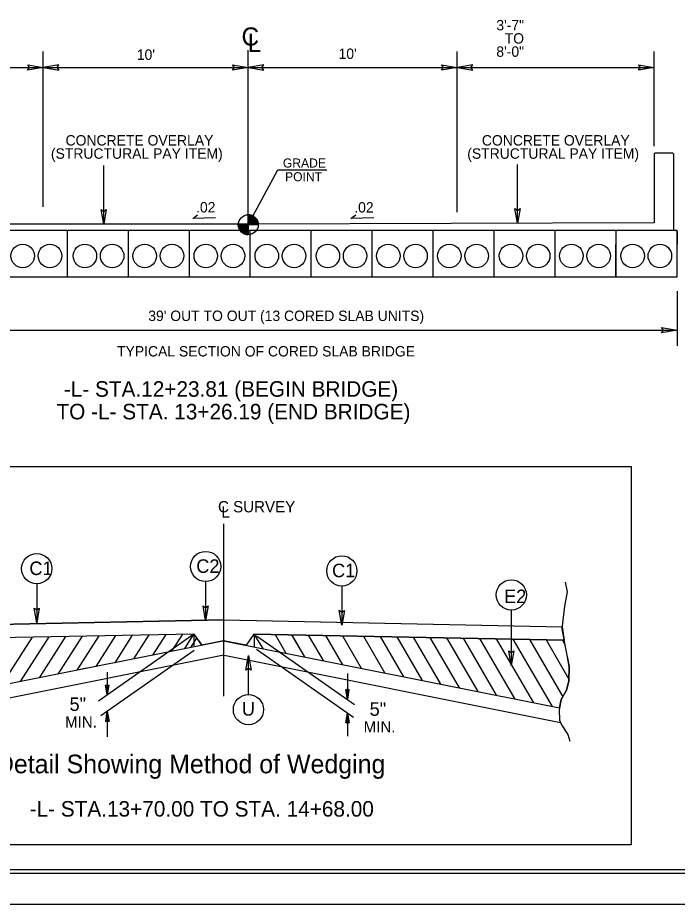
# Model space of a CAD drawing. Extents: x 1818040 to 1825768, y 638918 to 648046.
# Drawn here: x 1820696 to 1821171, y 645383 to 646022 of the extents above; entities that cross this region are included whole.
import ezdxf

# ---------------------------------------------------------------- set-up
doc = ezdxf.new("R2010")
doc.units = 0
for name, color, linetype in [('Default', 7, 'Continuous'), ('Old_Level_1', 7, 'Continuous'), ('Sheet Data Field CELL', 7, 'Continuous'), ('Sheet Plot Border Inside CELL', 7, 'Continuous'), ('Sheet Plot Border Outside CELL', 7, 'Continuous'), ('Sheet Typical CELL', 7, 'Continuous'), ('Typical Bridge Rail CELL', 7, 'Continuous'), ('Typical Detail Wedge2 CELL', 7, 'Continuous'), ('Typical Grade Point Symbol CELL', 7, 'Continuous'), ('Typical ID Circle CELL', 7, 'Continuous'), ('Typical Terminator CELL', 7, 'Continuous'), ('Typical Text Centerline CELL', 7, 'Continuous'), ('Typical Text General CELL', 7, 'Continuous'), ('Typical Text Grade Point CELL', 7, 'Continuous'), ('Typical Text ID Circle CELL', 7, 'Continuous')]:
    doc.layers.add(name, color=color, linetype=linetype)

msp = doc.modelspace()

# ---------------------------------------------------------------- linework, layer by layer
at = {"layer": 'Default'}
for p, q in [((1820714.57, 645885.64), (1820714.57, 645997.66)), ((1820862.17, 645872.84), (1820862.17, 645998.53)), ((1821012.56, 645881.99), (1821012.56, 645997.66)), ((1821154.38, 645929.41), (1821154.38, 645997.66)), ((1820619.19, 645986.11), (1820714.57, 645986.11)), ((1820714.57, 645986.11), (1820772.68, 645986.11)), ((1820772.68, 645986.11), (1820862.17, 645986.11)), ((1820862.17, 645986.11), (1820905.72, 645986.11)), ((1820905.72, 645986.11), (1821012.56, 645986.11)), ((1821012.56, 645986.11), (1821037.24, 645986.11)), ((1821037.24, 645986.11), (1821154.38, 645986.11)), ((1820758.09, 645873.14), (1820758.09, 645915.5)), ((1821056.03, 645873.89), (1821056.03, 645916.25)), ((1820862.17, 645872.84), (1820883.43, 645912.45)), ((1820822.22, 645877.37), (1820825.64, 645879.93)), ((1820838.66, 645877.75), (1820822.22, 645877.37)), ((1820936.12, 645877.3), (1820939.53, 645879.87)), ((1820952.56, 645877.69), (1820936.12, 645877.3)), ((1820602.6, 645869), (1821170.98, 645869)), ((1820862.17, 645873.14), (1820619.19, 645873.14)), ((1820731.69, 645869), (1820731.69, 645835.41)), ((1820775.59, 645869), (1820775.59, 645835.41)), ((1820819.49, 645869), (1820819.49, 645835.41)), ((1821154.38, 645874.27), (1820862.17, 645873.14)), ((1820863.39, 645869), (1820863.39, 645835.41)), ((1820907.29, 645869), (1820907.29, 645835.41)), ((1820951.19, 645869), (1820951.19, 645835.41)), ((1820995.09, 645869), (1820995.09, 645835.41)), ((1821038.99, 645869), (1821038.99, 645835.41)), ((1821082.89, 645869), (1821082.89, 645835.41)), ((1821126.93, 645869), (1821126.93, 645835.41)), ((1821170.98, 645835.41), (1821170.98, 645869)), ((1821126.93, 645835.41), (1821126.93, 645858.57)), ((1820602.6, 645835.41), (1821170.98, 645835.41)), ((1821170.98, 645824.95), (1821170.98, 645785.67)), ((1820602.56, 645796.99), (1821170.98, 645796.99))]:
    msp.add_line(p, q, dxfattribs=at)
for centre in [(1820699.72, 645850.36), (1820719.34, 645850.36), (1820744.52, 645850.36), (1820764.15, 645850.36), (1820787.62, 645850.36), (1820807.25, 645850.36), (1820831.57, 645850.36), (1820851.2, 645850.36), (1820875.52, 645850.36), (1820895.15, 645850.36), (1820919.47, 645850.36), (1820939.1, 645850.36), (1820962.99, 645850.36), (1820982.62, 645850.36), (1821006.94, 645850.36), (1821026.57, 645850.36), (1821051.32, 645850.36), (1821070.95, 645850.36), (1821094.84, 645850.36), (1821114.47, 645850.36), (1821138.89, 645850.36), (1821158.52, 645850.36)]:
    msp.add_circle(centre, 8.47, dxfattribs=at)
at = {"layer": 'Old_Level_1'}
msp.add_lwpolyline([(1820578.56, 645698.83), (1821137.94, 645698.83), (1821137.94, 645426.3), (1820578.56, 645426.3)], close=True, dxfattribs=at)
at = {"layer": 'Sheet Plot Border Inside CELL'}
msp.add_lwpolyline([(1822072.43, 646461.05), (1820405.93, 646461.05), (1820405.93, 645405.95), (1822072.43, 645405.95)], close=True, dxfattribs=at)
at = {"layer": 'Sheet Plot Border Outside CELL'}
msp.add_lwpolyline([(1822076.93, 646483.5), (1820392.93, 646483.5), (1820392.93, 645383.5), (1822076.93, 645383.5)], close=True, dxfattribs=at)
at = {"layer": 'Sheet Typical CELL'}
msp.add_line((1820392.93, 645383.5), (1822076.93, 645383.5), dxfattribs=at)
msp.add_lwpolyline([(1822059.93, 646458.5), (1820559.93, 646458.5), (1820559.93, 645408.5), (1822059.93, 645408.5)], close=True, dxfattribs=at)
at = {"layer": 'Typical Bridge Rail CELL'}
for p, q in [((1821154.38, 645923.89), (1821155.11, 645924.62)), ((1821154.38, 645923.89), (1821154.38, 645874.27)), ((1821155.11, 645924.62), (1821167.71, 645924.62)), ((1821167.71, 645924.62), (1821168.37, 645923.96)), ((1821168.37, 645923.96), (1821168.37, 645869)), ((1821168.37, 645869), (1821169.67, 645869)), ((1821169.67, 645869), (1821170.97, 645867.69)), ((1821170.97, 645867.69), (1821170.97, 645858.57))]:
    msp.add_line(p, q, dxfattribs=at)
at = {"layer": 'Typical Detail Wedge2 CELL'}
for p, q in [((1820844.67, 645533.44), (1820844.67, 645657.51)), ((1820844.67, 645533.44), (1820844.67, 645618.17)), ((1820844.66, 645588.25), (1820601.17, 645583.39)), ((1820601.17, 645583.39), (1820844.66, 645588.25)), ((1820844.66, 645588.25), (1821088.18, 645583.39)), ((1820844.69, 645588.25), (1821088.18, 645583.39)), ((1821088.18, 645583.39), (1821089.57, 645573.6)), ((1820823.31, 645578.07), (1820599.78, 645573.6)), ((1820823.31, 645578.07), (1820599.78, 645573.6)), ((1820706.45, 645575.74), (1820684.28, 645541.12)), ((1820718.48, 645575.98), (1820697.9, 645543.85)), ((1820730.51, 645576.22), (1820711.52, 645546.57)), ((1820742.54, 645576.46), (1820725.14, 645549.3)), ((1820754.57, 645576.7), (1820738.76, 645552.02)), ((1820766.59, 645576.94), (1820752.38, 645554.75)), ((1820823.03, 645577.89), (1820754.42, 645529.84)), ((1820778.62, 645577.18), (1820766, 645557.47)), ((1820790.65, 645577.42), (1820779.62, 645560.2)), ((1820802.68, 645577.66), (1820793.24, 645562.92)), ((1820814.71, 645577.9), (1820806.86, 645565.65)), ((1820816.39, 645567.66), (1820822.99, 645577.98)), ((1820825.05, 645575.51), (1820820.48, 645568.37)), ((1820822.99, 645577.98), (1820822.99, 645569.49)), ((1820828.78, 645570.05), (1820823.31, 645578.07)), ((1820823.31, 645577.81), (1820828.78, 645570.05)), ((1820866.21, 645578.07), (1820860.56, 645570.05)), ((1820866.21, 645578.07), (1820860.56, 645570.05)), ((1820865.85, 645577.89), (1820866.2, 645577.87)), ((1820866.21, 645578.07), (1821089.57, 645573.6)), ((1821089.57, 645573.6), (1820866.21, 645578.07)), ((1820872.96, 645567.66), (1820866.35, 645577.98)), ((1820866.35, 645577.98), (1820866.35, 645568.64)), ((1820868.07, 645576.77), (1820938.76, 645527.27)), ((1820881.44, 645577.77), (1820889.31, 645564.28)), ((1820893.39, 645577.53), (1820902.69, 645561.6)), ((1820893.59, 645577.25), (1820902.71, 645561.64)), ((1820905.34, 645577.29), (1820916.06, 645558.93)), ((1820917.75, 645577.04), (1820930, 645556.01)), ((1820929.91, 645576.8), (1820943.53, 645553.43)), ((1820945.13, 645576.49), (1820960.57, 645550.02)), ((1820957.08, 645576.25), (1820973.94, 645547.34)), ((1820969.03, 645576.01), (1820987.31, 645544.67)), ((1820980.98, 645575.78), (1821000.67, 645542)), ((1820992.92, 645575.54), (1821014.04, 645539.32)), ((1821004.87, 645575.3), (1821027.41, 645536.65)), ((1821016.82, 645575.06), (1821040.77, 645533.98)), ((1821028.76, 645574.82), (1821054.14, 645531.3)), ((1821040.71, 645574.58), (1821067.5, 645528.63)), ((1821052.66, 645574.34), (1821080.87, 645525.96)), ((1820845.03, 645573.28), (1820603, 645524.86)), ((1820844.31, 645573.28), (1820828.78, 645570.05)), ((1820844.31, 645573.28), (1821086.35, 645524.86)), ((1820860.56, 645570.05), (1820844.31, 645573.28)), ((1821064.6, 645574.1), (1821088.61, 645532.93)), ((1821076.55, 645573.86), (1821093.06, 645545.56)), ((1821088.5, 645573.63), (1821089.98, 645571.08)), ((1820844.58, 645562.86), (1820602.92, 645514.52)), ((1820823.19, 645566.15), (1820756.05, 645519.14)), ((1820844.76, 645562.86), (1821086.99, 645514.41)), ((1820867.97, 645567.15), (1820937.97, 645518.15)), ((1820745.78, 645553.43), (1820738.15, 645551.9)), ((1820760.67, 645550.54), (1820760.67, 645534.23)), ((1820933.59, 645549.6), (1820933.59, 645530.9)), ((1820760.67, 645534.23), (1820759.41, 645541.38)), ((1820760.67, 645540.45), (1820759.41, 645541.38)), ((1820760.67, 645534.23), (1820759.59, 645541.24)), ((1820759.77, 645541.11), (1820760.67, 645534.23)), ((1820760.67, 645534.23), (1820759.95, 645540.98)), ((1820760.13, 645540.85), (1820760.67, 645534.23)), ((1820760.67, 645534.23), (1820760.31, 645540.72)), ((1820760.49, 645540.58), (1820760.67, 645534.23)), ((1820760.67, 645534.23), (1820761.94, 645541.38)), ((1820761.94, 645541.38), (1820760.67, 645540.45)), ((1820761.76, 645541.24), (1820760.67, 645534.23)), ((1820760.67, 645534.23), (1820761.57, 645541.11)), ((1820761.39, 645540.98), (1820760.67, 645534.23)), ((1820760.67, 645534.23), (1820761.21, 645540.85)), ((1820761.03, 645540.72), (1820760.67, 645534.23)), ((1820760.67, 645534.23), (1820760.85, 645540.58)), ((1820760.67, 645540.45), (1820760.67, 645534.23)), ((1820933.59, 645530.9), (1820932.33, 645538.06)), ((1820933.59, 645537.13), (1820932.33, 645538.06)), ((1820933.59, 645530.9), (1820932.51, 645537.92)), ((1820932.69, 645537.79), (1820933.59, 645530.9)), ((1820933.59, 645530.9), (1820932.87, 645537.65)), ((1820933.04, 645537.52), (1820933.59, 645530.9)), ((1820933.59, 645530.9), (1820933.22, 645537.39)), ((1820933.4, 645537.26), (1820933.59, 645530.9)), ((1820933.59, 645530.9), (1820934.85, 645538.06)), ((1820934.85, 645538.06), (1820933.59, 645537.13)), ((1820934.66, 645537.92), (1820933.59, 645530.9)), ((1820933.59, 645530.9), (1820934.49, 645537.79)), ((1820934.31, 645537.65), (1820933.59, 645530.9)), ((1820933.59, 645530.9), (1820934.13, 645537.52)), ((1820933.95, 645537.39), (1820933.59, 645530.9)), ((1820933.59, 645530.9), (1820933.77, 645537.26)), ((1820933.59, 645537.13), (1820933.59, 645530.9)), ((1820760.67, 645522.37), (1820759.41, 645515.21)), ((1820759.59, 645515.35), (1820760.67, 645522.37)), ((1820760.67, 645522.37), (1820759.77, 645515.48)), ((1820759.95, 645515.62), (1820760.67, 645522.37)), ((1820760.67, 645522.37), (1820760.13, 645515.75)), ((1820760.31, 645515.87), (1820760.67, 645522.37)), ((1820760.67, 645522.37), (1820760.49, 645516.01)), ((1820760.67, 645522.37), (1820760.67, 645504)), ((1820760.67, 645522.37), (1820761.94, 645515.21)), ((1820760.67, 645516.14), (1820760.67, 645522.37)), ((1820760.85, 645516.01), (1820760.67, 645522.37)), ((1820760.67, 645522.37), (1820761.03, 645515.87)), ((1820761.21, 645515.75), (1820760.67, 645522.37)), ((1820760.67, 645522.37), (1820761.39, 645515.62)), ((1820761.57, 645515.48), (1820760.67, 645522.37)), ((1820760.67, 645522.37), (1820761.76, 645515.35)), ((1820933.59, 645521.21), (1820932.33, 645514.05)), ((1820932.51, 645514.19), (1820933.59, 645521.21)), ((1820933.59, 645521.21), (1820932.69, 645514.32)), ((1820932.87, 645514.46), (1820933.59, 645521.21)), ((1820933.59, 645521.21), (1820933.04, 645514.59)), ((1820933.22, 645514.71), (1820933.59, 645521.21)), ((1820933.59, 645521.21), (1820933.4, 645514.85)), ((1820933.59, 645521.21), (1820933.59, 645504.47)), ((1820933.59, 645521.21), (1820934.85, 645514.05)), ((1820933.59, 645514.98), (1820933.59, 645521.21)), ((1820933.77, 645514.85), (1820933.59, 645521.21)), ((1820933.59, 645521.21), (1820933.95, 645514.71)), ((1820934.13, 645514.59), (1820933.59, 645521.21)), ((1820933.59, 645521.21), (1820934.31, 645514.46)), ((1820934.49, 645514.32), (1820933.59, 645521.21)), ((1820933.59, 645521.21), (1820934.66, 645514.19)), ((1820759.41, 645515.21), (1820760.67, 645516.14)), ((1820760.67, 645516.14), (1820761.94, 645515.21)), ((1820932.33, 645514.05), (1820933.59, 645514.98)), ((1820933.59, 645514.98), (1820934.85, 645514.05))]:
    msp.add_line(p, q, dxfattribs=at)
for points in [[(1821090.43, 645615.52), (1821091.73, 645608.39), (1821089.79, 645598.25), (1821088.06, 645581.83), (1821090.43, 645568.87), (1821093.24, 645554.83), (1821093.03, 645544.24), (1821091.29, 645537.56), (1821087.41, 645530.85), (1821086.12, 645523.51), (1821086.32, 645516.17), (1821087.62, 645512.71), (1821092.15, 645505.79), (1821093.66, 645501.04)], [(1821086.35, 645524.86), (1821087.41, 645530.85), (1821091.29, 645537.56), (1821093.03, 645544.24), (1821093.24, 645554.83), (1821091.94, 645561.34)]]:
    msp.add_lwpolyline(points, dxfattribs=at)
at = {"layer": 'Typical Grade Point Symbol CELL'}
for p, q in [((1820862.17, 645872.84), (1820862.17, 645880)), ((1820855.01, 645872.84), (1820862.17, 645872.84)), ((1820862.15, 645865.68), (1820862.17, 645872.84)), ((1820862.17, 645872.84), (1820862.15, 645865.68)), ((1820869.33, 645872.84), (1820862.17, 645872.84))]:
    msp.add_line(p, q, dxfattribs=at)
for points in [[(1820862.23, 645880), (1820862.23, 645880), (1820862.23, 645872.84)], [(1820862.37, 645880), (1820862.37, 645872.84)], [(1820862.52, 645879.98), (1820862.52, 645872.84)], [(1820862.66, 645879.98), (1820862.66, 645872.84)], [(1820862.8, 645879.97), (1820862.8, 645872.84)], [(1820862.95, 645879.95), (1820862.95, 645872.84)], [(1820863.09, 645879.93), (1820863.09, 645872.84)], [(1820863.23, 645879.92), (1820863.23, 645872.84)], [(1820863.38, 645879.9), (1820863.38, 645872.84)], [(1820863.52, 645879.87), (1820863.52, 645872.84)], [(1820863.66, 645879.84), (1820863.66, 645872.84)], [(1820863.81, 645879.81), (1820863.81, 645872.84)], [(1820863.95, 645879.78), (1820863.95, 645872.84)], [(1820864.09, 645879.73), (1820864.09, 645872.84)], [(1820864.24, 645879.7), (1820864.24, 645872.84)], [(1820864.38, 645879.65), (1820864.38, 645872.84)], [(1820864.52, 645879.6), (1820864.52, 645872.84)], [(1820864.67, 645879.55), (1820864.67, 645872.84)], [(1820864.81, 645879.49), (1820864.81, 645872.84)], [(1820864.95, 645879.43), (1820864.95, 645872.84)], [(1820865.1, 645879.36), (1820865.1, 645872.84)], [(1820865.24, 645879.3), (1820865.24, 645872.84)], [(1820865.38, 645879.23), (1820865.38, 645872.84)], [(1820865.52, 645879.15), (1820865.52, 645872.84)], [(1820865.67, 645879.08), (1820865.67, 645872.84)], [(1820865.81, 645879), (1820865.81, 645872.84)], [(1820865.95, 645878.92), (1820865.95, 645872.84)], [(1820866.1, 645878.82), (1820866.1, 645872.84)], [(1820866.24, 645878.72), (1820866.24, 645872.84)], [(1820866.38, 645878.61), (1820866.38, 645872.84)], [(1820866.53, 645878.52), (1820866.53, 645872.84)], [(1820866.67, 645878.41), (1820866.67, 645872.84)], [(1820866.81, 645878.28), (1820866.81, 645872.84)], [(1820866.96, 645878.15), (1820866.96, 645872.84)], [(1820867.1, 645878.02), (1820867.1, 645872.84)], [(1820867.24, 645877.88), (1820867.24, 645872.84)], [(1820867.39, 645877.74), (1820867.39, 645872.84)], [(1820867.53, 645877.58), (1820867.53, 645872.84)], [(1820867.67, 645877.4), (1820867.67, 645872.84)], [(1820867.82, 645877.23), (1820867.82, 645872.84)], [(1820867.96, 645877.04), (1820867.96, 645872.84)], [(1820868.1, 645876.83), (1820868.1, 645872.84)], [(1820868.25, 645876.61), (1820868.25, 645872.84)], [(1820868.39, 645876.37), (1820868.39, 645872.84)], [(1820868.53, 645876.12), (1820868.53, 645872.84)], [(1820868.68, 645875.81), (1820868.68, 645872.84)], [(1820868.82, 645875.48), (1820868.82, 645872.84)], [(1820868.96, 645875.08), (1820868.96, 645872.84)], [(1820869.11, 645874.59), (1820869.11, 645872.84)], [(1820855.04, 645872.84), (1820855.04, 645872.06)], [(1820855.18, 645872.84), (1820855.18, 645871.21)], [(1820855.32, 645872.84), (1820855.32, 645870.7)], [(1820855.47, 645872.84), (1820855.47, 645870.27)], [(1820855.61, 645872.84), (1820855.61, 645869.94)], [(1820855.75, 645872.84), (1820855.75, 645869.64)], [(1820855.9, 645872.84), (1820855.9, 645869.37)], [(1820856.04, 645872.84), (1820856.04, 645869.11)], [(1820856.18, 645872.84), (1820856.18, 645868.89)], [(1820856.33, 645872.84), (1820856.33, 645868.68)], [(1820856.47, 645872.84), (1820856.47, 645868.49)], [(1820856.61, 645872.84), (1820856.61, 645868.32)], [(1820856.76, 645872.84), (1820856.76, 645868.14)], [(1820856.9, 645872.84), (1820856.9, 645867.98)], [(1820857.04, 645872.84), (1820857.04, 645867.82)], [(1820857.19, 645872.84), (1820857.19, 645867.68)], [(1820857.33, 645872.84), (1820857.33, 645867.55)], [(1820857.47, 645872.84), (1820857.47, 645867.43)], [(1820857.62, 645872.84), (1820857.62, 645867.3)], [(1820857.76, 645872.84), (1820857.76, 645867.19)], [(1820857.9, 645872.84), (1820857.9, 645867.08)], [(1820858.05, 645872.84), (1820858.05, 645866.98)], [(1820858.19, 645872.84), (1820858.19, 645866.88)], [(1820858.33, 645872.84), (1820858.33, 645866.79)], [(1820858.48, 645872.84), (1820858.48, 645866.69)], [(1820858.62, 645872.84), (1820858.62, 645866.61)], [(1820858.76, 645872.84), (1820858.76, 645866.53)], [(1820858.91, 645872.84), (1820858.91, 645866.45)], [(1820859.05, 645872.84), (1820859.05, 645866.39)], [(1820859.19, 645872.84), (1820859.19, 645866.33)], [(1820859.34, 645872.84), (1820859.34, 645866.26)], [(1820859.48, 645872.84), (1820859.48, 645866.2)], [(1820859.62, 645872.84), (1820859.62, 645866.14)], [(1820859.76, 645872.84), (1820859.76, 645866.09)], [(1820859.91, 645872.84), (1820859.91, 645866.04)], [(1820860.05, 645872.84), (1820860.05, 645865.99)], [(1820860.19, 645872.84), (1820860.19, 645865.96)], [(1820860.34, 645872.84), (1820860.34, 645865.91)], [(1820860.48, 645872.84), (1820860.48, 645865.88)], [(1820860.62, 645872.84), (1820860.62, 645865.85)], [(1820860.77, 645872.84), (1820860.77, 645865.82)], [(1820860.91, 645872.84), (1820860.91, 645865.79)], [(1820861.05, 645872.84), (1820861.05, 645865.77)], [(1820861.2, 645872.84), (1820861.2, 645865.74)], [(1820861.34, 645872.84), (1820861.34, 645865.72)], [(1820861.48, 645872.84), (1820861.48, 645865.71)], [(1820861.63, 645872.84), (1820861.63, 645865.69)], [(1820861.77, 645872.84), (1820861.77, 645865.69)], [(1820861.91, 645872.84), (1820861.91, 645865.68)], [(1820862.06, 645872.84), (1820862.06, 645865.68), (1820862.06, 645865.68)], [(1820869.25, 645873.86), (1820869.25, 645872.84)]]:
    msp.add_lwpolyline(points, dxfattribs=at)
msp.add_circle((1820862.16, 645872.84), 7.16, dxfattribs=at)
for start, end in [(359.99048, 89.99048), (179.99048, 269.99048)]:
    msp.add_arc((1820862.16, 645872.84), 7.16, start, end, dxfattribs=at)
at = {"layer": 'Typical ID Circle CELL'}
for p, q in [((1820709.84, 645614.29), (1820709.84, 645586.18)), ((1820831.45, 645615.86), (1820831.45, 645587.75)), ((1820929.55, 645612.67), (1820929.55, 645584.57)), ((1821051.57, 645595.4), (1821051.57, 645555.43)), ((1820862.29, 645534.51), (1820862.29, 645562.62))]:
    msp.add_line(p, q, dxfattribs=at)
for centre in [(1820709.85, 645625.16), (1820831.45, 645626.73), (1820929.55, 645623.55), (1821051.56, 645606.27), (1820862.29, 645523.64)]:
    msp.add_circle(centre, 10.88, dxfattribs=at)
at = {"layer": 'Typical Terminator CELL'}
for points in [[(1820703.32, 645988.05), (1820714.57, 645986.11), (1820703.25, 645984.11), (1820704.69, 645986.11)], [(1820725.81, 645988.05), (1820714.57, 645986.11), (1820725.88, 645984.11), (1820724.44, 645986.11)], [(1820850.92, 645988.05), (1820862.17, 645986.11), (1820850.86, 645984.11), (1820852.29, 645986.11)], [(1820873.42, 645988.05), (1820862.17, 645986.11), (1820873.48, 645984.11), (1820872.04, 645986.11)], [(1821001.31, 645988.05), (1821012.56, 645986.11), (1821001.25, 645984.11), (1821002.68, 645986.11)], [(1821023.81, 645988.05), (1821012.56, 645986.11), (1821023.87, 645984.11), (1821022.43, 645986.11)], [(1821143.14, 645988.05), (1821154.38, 645986.11), (1821143.07, 645984.11), (1821144.51, 645986.11)], [(1820759.9, 645883.69), (1820758.09, 645873.14), (1820756.21, 645883.75), (1820758.09, 645882.4)], [(1821057.85, 645884.44), (1821056.03, 645873.89), (1821054.16, 645884.5), (1821056.03, 645883.15)], [(1821159.73, 645798.93), (1821170.98, 645796.99), (1821159.67, 645794.99), (1821161.1, 645796.99)], [(1820711.66, 645596.73), (1820709.84, 645586.18), (1820707.97, 645596.78), (1820709.84, 645595.44)], [(1820711.66, 645596.73), (1820709.84, 645586.18), (1820707.97, 645596.78), (1820709.84, 645595.44)], [(1820833.27, 645598.29), (1820831.45, 645587.75), (1820829.58, 645598.35), (1820831.45, 645597)], [(1820833.27, 645598.29), (1820831.45, 645587.75), (1820829.58, 645598.35), (1820831.45, 645597)], [(1820931.37, 645595.11), (1820929.55, 645584.57), (1820927.67, 645595.17), (1820929.55, 645593.82)], [(1820860.47, 645552.07), (1820862.29, 645562.62), (1820864.17, 645552.02), (1820862.29, 645553.36)], [(1820860.47, 645552.07), (1820862.29, 645562.62), (1820864.17, 645552.02), (1820862.29, 645553.36)], [(1821053.38, 645565.98), (1821051.57, 645555.43), (1821049.69, 645566.04), (1821051.57, 645564.69)]]:
    msp.add_lwpolyline(points, close=True, dxfattribs=at)
at = {"layer": 'Typical Text Grade Point CELL'}
msp.add_line((1820883.43, 645912.45), (1820918.81, 645912.45), dxfattribs=at)

# ---------------------------------------------------------------- texts
at = {"layer": 'Sheet Data Field CELL'}
for s, p in [('3\'-7" ', (1821040.78, 646012.77)), ('TO ', (1821046.8, 646003.26)), ("10'", (1820781.9, 645991.53)), ("10'", (1820927.17, 645992.2)), ('8\'-0"', (1821040.78, 645993.76)), ('CONCRETE OVERLAY', (1820730.59, 645929.84)), ('CONCRETE OVERLAY', (1821030.38, 645929.84)), ('(STRUCTURAL PAY ITEM)', (1820720.06, 645920.34)), ('(STRUCTURAL PAY ITEM)', (1821019.84, 645920.34)), ('.02', (1820824.58, 645881.66)), ('.02', (1820938.47, 645881.6)), ("39' OUT TO OUT (13 CORED SLAB UNITS)", (1820790.15, 645803.5)), ('TYPICAL SECTION OF CORED SLAB BRIDGE', (1820767.67, 645777.95))]:
    msp.add_text(s, height=7.5, dxfattribs=at).set_placement(p)
at = {"layer": 'Typical Detail Wedge2 CELL'}
for s, height, p in [('5"', 9.735, (1820733.49, 645522.71)), ('5"', 9.735, (1820949.56, 645519.18)), ('MIN.', 8.135, (1820730.22, 645510.75)), ('MIN.', 8.135, (1820945.21, 645507.21))]:
    msp.add_text(s, height=height, dxfattribs=at).set_placement(p)
at = {"layer": 'Typical Text Centerline CELL'}
for s, height, p in [('C', 13.12, (1820857.3, 646001.79)), ('C SURVEY ', 8.135, (1820840.37, 645665.7)), ('L', 8.13, (1820842.75, 645661.89))]:
    msp.add_text(s, height=height, dxfattribs=at).set_placement(p)
msp.add_text('L', height=13.13, rotation=359.9469, dxfattribs=at).set_placement((1820861.66, 645997.31))
at = {"layer": 'Typical Text General CELL'}
msp.add_text('Detail Showing Method of Wedging', height=13.4275, dxfattribs=at).set_placement((1820680.43, 645477.81))
at = {"layer": 'Typical Text Grade Point CELL'}
for s, height, p in [('GRADE', 6.525, (1820887.07, 645914.01)), ('POINT', 6.525, (1820888.64, 645904.13)), ('-L- STA.12+23.81 (BEGIN BRIDGE)', 11.1896, (1820729.37, 645748.96)), (' TO -L- STA. 13+26.19 (END BRIDGE)  ', 11.1896, (1820719.89, 645732.66)), ('-L- STA.13+70.00 TO STA. 14+68.00', 11.1896, (1820704.73, 645446.62))]:
    msp.add_text(s, height=height, dxfattribs=at).set_placement(p)
at = {"layer": 'Typical Text ID Circle CELL'}
for s, height, p in [('C2', 9.735, (1820824.74, 645622.13)), ('C1', 9.735, (1820704.56, 645620.57)), ('C1', 9.735, (1820922.52, 645618.99)), ('E2', 9.735, (1821046.41, 645600.35)), ('U', 9.73, (1820857.54, 645519.33))]:
    msp.add_text(s, height=height, dxfattribs=at).set_placement(p)

doc.saveas('drawing.dxf')
